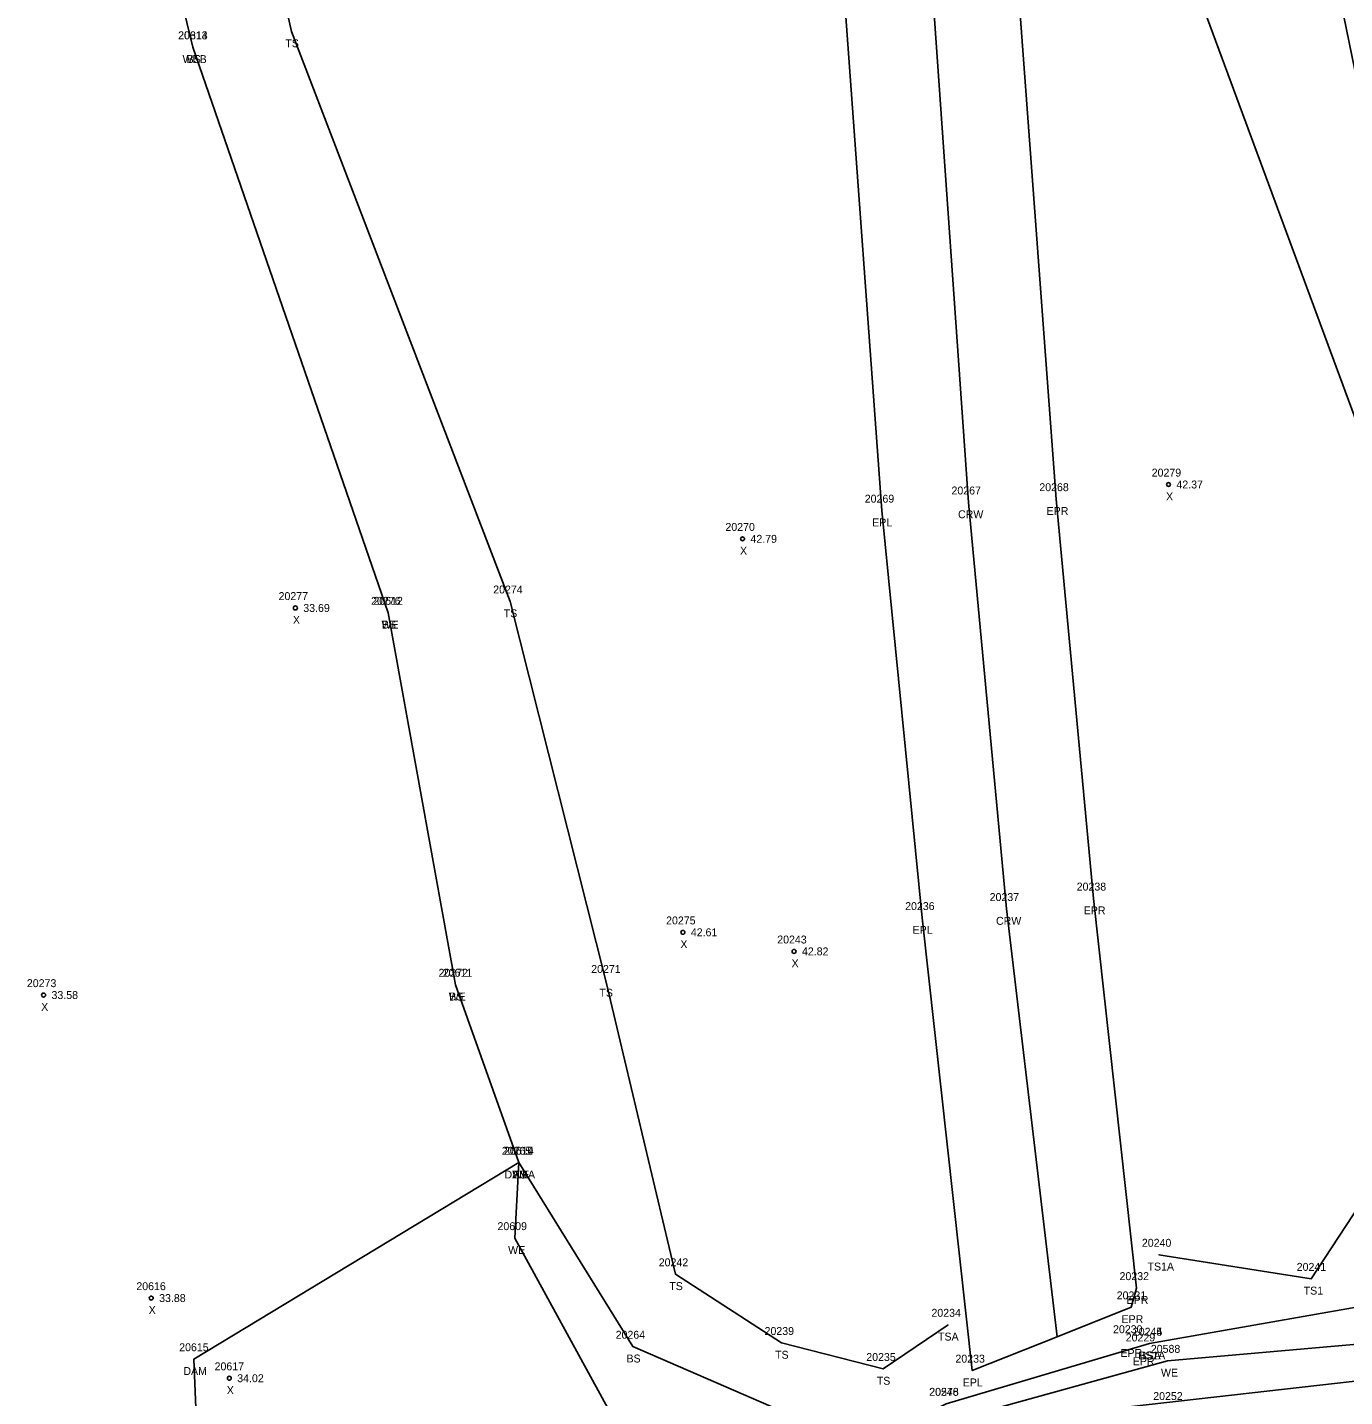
# Model space of a CAD drawing. Extents: x 2445178 to 2446260, y 791158 to 792318.
# Drawn here: x 2445580.3 to 2445746.6, y 791810 to 791982.9 of the extents above; entities that cross this region are included whole.
import ezdxf

# ---------------------------------------------------------------- set-up
doc = ezdxf.new("R2010")
doc.units = 0
for name, color, linetype in [('RD_DTM_BkLn1', 7, 'Continuous'), ('RD_DTM_BkLn2', 7, 'Continuous'), ('RD_EX_Dam', 7, 'Continuous'), ('RD_EX_Dam_txCode', 7, 'Continuous'), ('RD_EX_H2O', 7, 'Continuous'), ('RD_EX_H2O_txCode', 7, 'Continuous'), ('RD_EX_Road', 7, 'Continuous'), ('RD_EX_Road_txCode', 7, 'Continuous'), ('RD_Sketch8', 7, 'Continuous'), ('RD_SMD_Locator', 7, 'Continuous'), ('RD_SMD_Misc', 7, 'Continuous')]:
    doc.layers.add(name, color=color, linetype=linetype)

msp = doc.modelspace()

# ---------------------------------------------------------------- linework, layer by layer
at = {"layer": 'RD_DTM_BkLn1'}
for points in [[(2445710.31, 791817.61), (2445703.89, 791871.62), (2445699.09, 791922.95), (2445694.51, 791988.23), (2445692.28, 792033.16), (2445689.82, 792090.63), (2445687.08, 792198.77), (2445684.85, 792300.91)], [(2445719.65, 791821.33), (2445710.31, 791817.61), (2445699.57, 791813.34)]]:
    msp.add_lwpolyline(points, dxfattribs=at)
at = {"layer": 'RD_DTM_BkLn2'}
for points in [[(2445721.97, 791816.74), (2445696.27, 791809.15), (2445685.63, 791803.83), (2445656.7, 791816.36), (2445642.32, 791839.59), (2445634.31, 791862.06), (2445625.81, 791909.02), (2445601.16, 791980.42), (2445587.75, 792035.69), (2445589.15, 792093.24), (2445629.12, 792201.55), (2445634.25, 792303.36)], [(2445696.53, 791819.13), (2445688.31, 791813.55), (2445675.47, 791816.83), (2445662.11, 791825.5), (2445653.3, 791862.54), (2445641.21, 791910.45), (2445613.64, 791982.42), (2445601.35, 792036.55), (2445604.5, 792093.32), (2445645.58, 792199.83), (2445656.44, 792300.62)], [(2445721.97, 791816.74), (2445749.98, 791821.69), (2445763.92, 791830.66), (2445773.82, 791855.25), (2445775.82, 791885.45), (2445758.38, 791926.24), (2445744.75, 791992.74), (2445740.15, 792016.85)], [(2445723.15, 791827.97), (2445742.38, 791824.93), (2445764.31, 791858.33), (2445764.27, 791888.69), (2445750.79, 791925.83), (2445727.01, 791990.21), (2445728.86, 792017.77)]]:
    msp.add_lwpolyline(points, dxfattribs=at)
at = {"layer": 'RD_EX_Dam'}
msp.add_lwpolyline([(2445642.32, 791839.59), (2445601.3, 791814.78), (2445603.08, 791770.94), (2445606.78, 791746.54), (2445612.18, 791734.98)], dxfattribs=at)
at = {"layer": 'RD_EX_H2O'}
for points in [[(2445757.3, 791817.48), (2445724.23, 791814.58), (2445698.23, 791807.38), (2445689.87, 791803.29), (2445658, 791800.52), (2445641.81, 791830.07), (2445642.32, 791839.59), (2445634.31, 791862.06), (2445625.81, 791909.02), (2445601.16, 791980.42)], [(2445756.08, 791812.92), (2445698.14, 791806.34), (2445651.88, 791781.68), (2445605.82, 791776.55)]]:
    msp.add_lwpolyline(points, dxfattribs=at)
at = {"layer": 'RD_EX_Road'}
for points in [[(2445719.65, 791821.33), (2445720.29, 791823.76), (2445714.87, 791872.94), (2445710.18, 791923.37), (2445705.3, 791989.12), (2445702.81, 792033.07), (2445700.66, 792091.77), (2445697.78, 792201.78), (2445695.41, 792302.8)], [(2445699.57, 791813.34), (2445693.24, 791870.48), (2445688.14, 791921.92), (2445683.42, 791987.19), (2445680.88, 792033.67), (2445678.74, 792090.55), (2445675.91, 792199.23), (2445673.61, 792301.11)]]:
    msp.add_lwpolyline(points, dxfattribs=at)
at = {"layer": 'RD_SMD_Locator'}
for centre, radius in [((2445613.64, 791982.42), 0.001), ((2445601.16, 791980.42), 0.001), ((2445601.16, 791980.42), 0.001), ((2445724.35, 791925.21), 0.25), ((2445710.18, 791923.37), 0.001), ((2445688.14, 791921.92), 0.001), ((2445699.09, 791922.95), 0.001), ((2445670.57, 791918.35), 0.25), ((2445614.11, 791909.62), 0.25), ((2445641.21, 791910.45), 0.001), ((2445625.81, 791909.02), 0.001), ((2445625.81, 791909.02), 0.001), ((2445714.87, 791872.94), 0.001), ((2445703.89, 791871.62), 0.001), ((2445693.24, 791870.48), 0.001), ((2445663.04, 791868.67), 0.25), ((2445677.07, 791866.26), 0.25), ((2445653.3, 791862.54), 0.001), ((2445582.32, 791860.75), 0.25), ((2445634.31, 791862.06), 0.001), ((2445634.31, 791862.06), 0.001), ((2445642.32, 791839.59), 0.001), ((2445642.32, 791839.59), 0.001), ((2445642.32, 791839.59), 0.001), ((2445641.81, 791830.07), 0.001), ((2445723.15, 791827.97), 0.001), ((2445662.11, 791825.5), 0.001), ((2445742.38, 791824.93), 0.001), ((2445720.29, 791823.76), 0.001), ((2445595.91, 791822.49), 0.25), ((2445719.65, 791821.33), 0.001), ((2445696.53, 791819.13), 0.001), ((2445656.7, 791816.36), 0.001), ((2445675.47, 791816.83), 0.001), ((2445721.97, 791816.74), 0.001), ((2445721.97, 791816.74), 0.001), ((2445601.3, 791814.78), 0.001), ((2445724.23, 791814.58), 0.001), ((2445605.77, 791812.37), 0.25), ((2445688.31, 791813.55), 0.001), ((2445699.57, 791813.34), 0.001)]:
    msp.add_circle(centre, radius, dxfattribs=at)

# ---------------------------------------------------------------- texts
at = {"layer": 'RD_EX_Dam_txCode'}
for s, p in [('20614', (2445640.47, 791840.59)), ('DAMA', (2445640.51, 791837.59)), ('20615', (2445599.44, 791815.78)), ('DAM', (2445599.97, 791812.78))]:
    msp.add_text(s, height=1, dxfattribs=at).set_placement(p)
at = {"layer": 'RD_EX_H2O_txCode'}
for s, p in [('20613', (2445599.3, 791981.42)), ('WEB', (2445599.87, 791978.42)), ('20612', (2445623.96, 791910.02)), ('WE', (2445624.98, 791907.02)), ('20611', (2445632.73, 791863.06)), ('WE', (2445633.47, 791860.06)), ('20610', (2445640.43, 791840.59)), ('WE', (2445641.49, 791837.59)), ('20609', (2445639.63, 791831.07)), ('WE', (2445640.97, 791828.07)), ('20588', (2445722.12, 791815.58)), ('WE', (2445723.4, 791812.58)), ('20578', (2445694.15, 791810.15))]:
    msp.add_text(s, height=1, dxfattribs=at).set_placement(p)
at = {"layer": 'RD_EX_Road_txCode'}
for s, p in [('20268', (2445708.04, 791924.37)), ('20269', (2445686, 791922.92)), ('EPR', (2445708.96, 791921.37)), ('EPL', (2445686.94, 791919.92)), ('20238', (2445712.76, 791873.94)), ('20236', (2445691.1, 791871.48)), ('EPR', (2445713.65, 791870.94)), ('EPL', (2445692.04, 791868.48)), ('20232', (2445718.17, 791824.76)), ('20231', (2445717.81, 791822.33)), ('EPR', (2445719.06, 791821.76)), ('EPR', (2445718.42, 791819.33)), ('20230', (2445717.35, 791818.06)), ('20229', (2445718.95, 791817.02)), ('EPR', (2445718.28, 791815.06)), ('20233', (2445697.45, 791814.34)), ('EPR', (2445719.84, 791814.02)), ('EPL', (2445698.37, 791811.34))]:
    msp.add_text(s, height=1, dxfattribs=at).set_placement(p)
at = {"layer": 'RD_Sketch8'}
for s, p in [('20279', (2445722.23, 791926.21)), ('42.37', (2445725.35, 791924.71)), ('X', (2445724.04, 791923.21)), ('20270', (2445668.41, 791919.35)), ('42.79', (2445671.57, 791917.85)), ('X', (2445670.25, 791916.35)), ('20277', (2445611.99, 791910.62)), ('33.69', (2445615.11, 791909.12)), ('X', (2445613.8, 791907.62)), ('20275', (2445660.92, 791869.67)), ('42.61', (2445664.04, 791868.17)), ('20243', (2445674.95, 791867.26)), ('X', (2445662.72, 791866.67)), ('42.82', (2445678.07, 791865.76)), ('X', (2445676.76, 791864.26)), ('20273', (2445580.21, 791861.75)), ('33.58', (2445583.32, 791860.25)), ('X', (2445582.01, 791858.75)), ('20616', (2445594.03, 791823.49)), ('33.88', (2445596.91, 791821.99)), ('X', (2445595.59, 791820.49)), ('20617', (2445603.91, 791813.37)), ('34.02', (2445606.77, 791811.87)), ('X', (2445605.45, 791810.37)), ('20252', (2445722.42, 791809.62))]:
    msp.add_text(s, height=1, dxfattribs=at).set_placement(p)
at = {"layer": 'RD_SMD_Misc'}
for s, p in [('20314', (2445599.32, 791981.42)), ('TS', (2445612.84, 791980.42)), ('BS', (2445600.38, 791978.42)), ('20267', (2445696.95, 791923.95)), ('CRW', (2445697.78, 791920.95)), ('20276', (2445623.67, 791910.02)), ('20274', (2445639.09, 791911.45)), ('TS', (2445640.42, 791908.45)), ('BS', (2445625.03, 791907.02)), ('20237', (2445701.77, 791872.62)), ('CRW', (2445702.57, 791869.62)), ('20271', (2445651.46, 791863.54)), ('20272', (2445632.19, 791863.06)), ('BS', (2445633.53, 791860.06)), ('TS', (2445652.5, 791860.54)), ('20265', (2445640.18, 791840.59)), ('BS', (2445641.54, 791837.59)), ('20240', (2445720.99, 791828.97)), ('20242', (2445659.99, 791826.5)), ('TS1A', (2445721.7, 791825.97)), ('20241', (2445740.54, 791825.93)), ('TS', (2445661.32, 791823.5)), ('TS1', (2445741.42, 791822.93)), ('20234', (2445694.42, 791820.13)), ('20264', (2445654.55, 791817.36)), ('20239', (2445673.35, 791817.83)), ('TSA', (2445695.25, 791817.13)), ('20244', (2445719.85, 791817.74)), ('20245', (2445719.85, 791817.74)), ('TS', (2445674.68, 791814.83)), ('BS', (2445655.92, 791814.36)), ('20235', (2445686.19, 791814.55)), ('BS1A', (2445720.53, 791814.74)), ('BSA', (2445720.7, 791814.74)), ('TS', (2445687.52, 791811.55)), ('20246', (2445694.13, 791810.15))]:
    msp.add_text(s, height=1, dxfattribs=at).set_placement(p)

doc.saveas('drawing.dxf')
